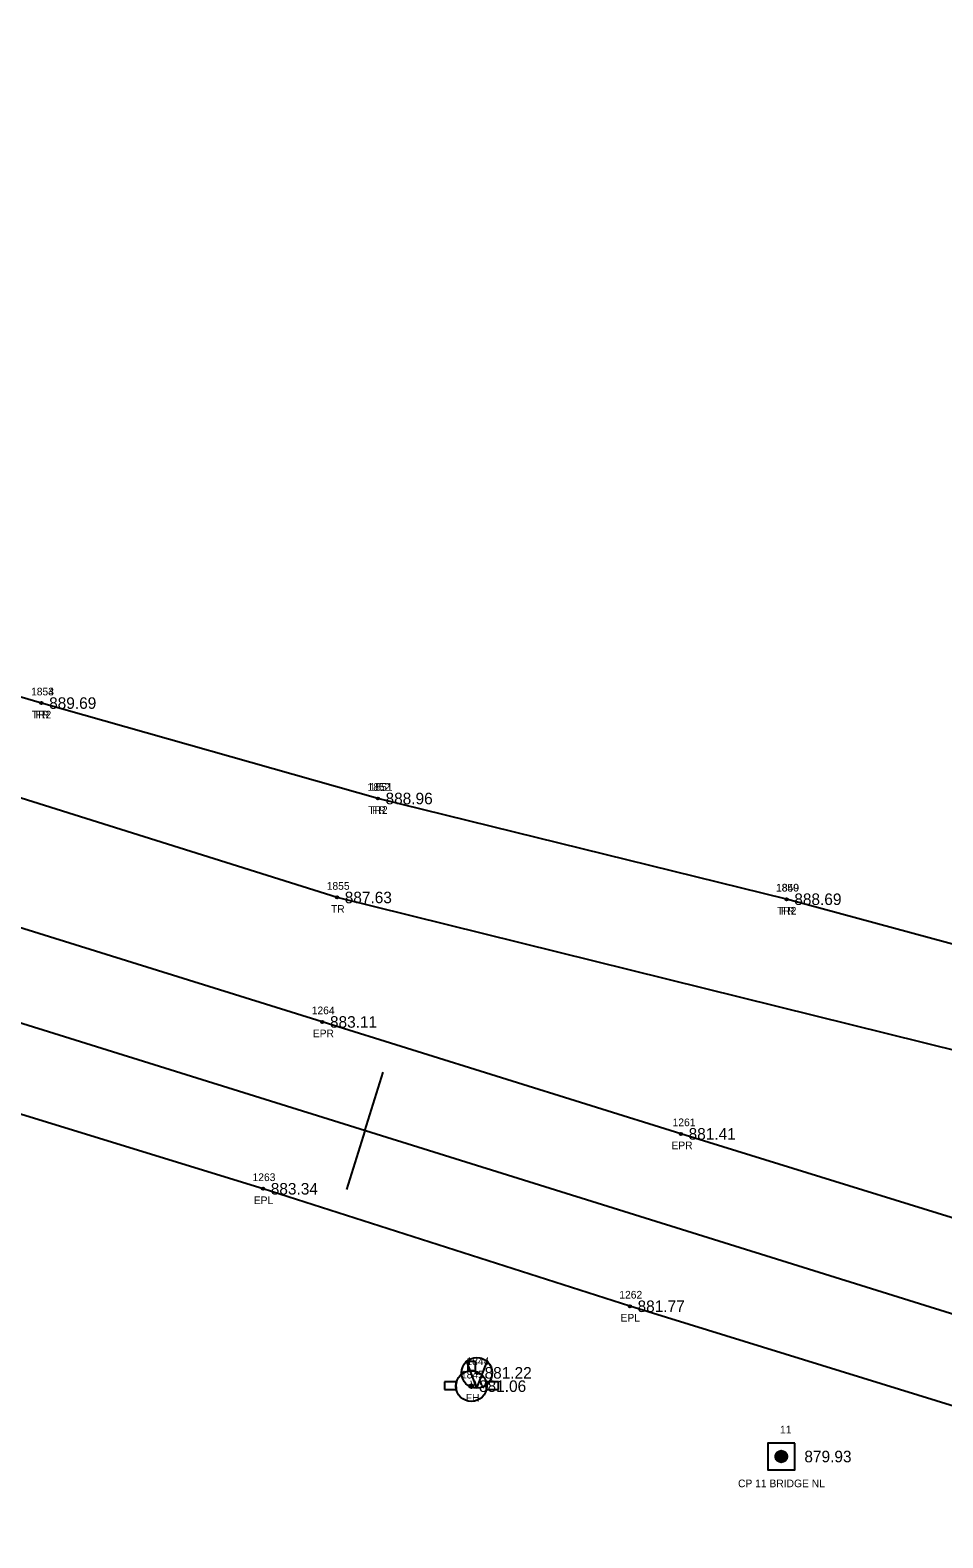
# Model space of a CAD drawing. Extents: x 1448136 to 1453623, y 1125056 to 1128842.
# Drawn here: x 1449871.2 to 1449990, y 1126660.1 to 1126856.2 of the extents above; entities that cross this region are included whole.
import ezdxf

# ---------------------------------------------------------------- set-up
doc = ezdxf.new("R2010")
doc.units = 0
for name, color, linetype in [('RD_EX_Fence_Other', 7, 'Continuous'), ('RD_EX_Fence_Other_txCode', 7, 'Continuous'), ('RD_EX_Road', 7, 'Continuous'), ('RD_EX_Road_txCode', 7, 'Continuous'), ('RD_EX_TX_Fence_Other_ELEV', 7, 'Continuous'), ('RD_EX_TX_Road_ELEV', 7, 'Continuous'), ('RD_EX_TX_UT_ELEV', 7, 'Continuous'), ('RD_EX_TX_VEG_ELEV', 7, 'Continuous'), ('RD_EX_UT', 7, 'Continuous'), ('RD_EX_UT_txCode', 7, 'Continuous'), ('RD_EX_VEG', 7, 'Continuous'), ('RD_EX_VEG_txCode', 7, 'Continuous'), ('RD_HC_Cl', 7, 'Continuous'), ('RD_HC_Data_Tic', 7, 'Continuous'), ('RD_HC_Survey', 7, 'Continuous'), ('RD_HC_Survey_ELEV', 7, 'Continuous'), ('RD_HC_Survey_txCode', 7, 'Continuous'), ('RD_SMD_Locator', 7, 'Continuous')]:
    doc.layers.add(name, color=color, linetype=linetype)

msp = doc.modelspace()

# ---------------------------------------------------------------- linework, layer by layer
at = {"layer": 'RD_EX_Fence_Other'}
msp.add_lwpolyline([(1450056.89, 1126784.04), (1450047.15, 1126748.04), (1450041.18, 1126724.82), (1450011.35, 1126731.86), (1449969.63, 1126743.17), (1449916.46, 1126756.27), (1449872.7, 1126768.68), (1449825.21, 1126782.55), (1449770.87, 1126786.35)], dxfattribs=at)
at = {"layer": 'RD_EX_Road'}
for points in [[(1450334.81, 1126677.22), (1450288.34, 1126667.77), (1450239.92, 1126662.52), (1450192.72, 1126661.45), (1450145.26, 1126665.09), (1450097.34, 1126672.81), (1450049.7, 1126684.25), (1450007.41, 1126696.7), (1449955.88, 1126712.65), (1449909.23, 1126727.21), (1449862.31, 1126741.85), (1449813.73, 1126756.84), (1449766.18, 1126771.72), (1449717.33, 1126787.19), (1449671.79, 1126801.4), (1449624.98, 1126815.8), (1449576.84, 1126830.74), (1449569.21, 1126834.03), (1449511.24, 1126851.67), (1449482.54, 1126860.68), (1449432.31, 1126877.02)], [(1450340.73, 1126655.01), (1450291.74, 1126645.33), (1450242.07, 1126639.91), (1450191.92, 1126637.95), (1450184.99, 1126636.16), (1450163.38, 1126634.92), (1450141.93, 1126638.08), (1450123.3, 1126641.98), (1450121.61, 1126644.88), (1450093.17, 1126650), (1450044.99, 1126661.93), (1449996.8, 1126675.54), (1449949.24, 1126690.23), (1449901.53, 1126705.51), (1449854.27, 1126720.01), (1449807.04, 1126735.02), (1449759.58, 1126749.86), (1449712.08, 1126764.7), (1449664.51, 1126779.32), (1449616.94, 1126794.11), (1449569.36, 1126808.87), (1449521.79, 1126823.57), (1449474.36, 1126838.35), (1449426.72, 1126853.6)]]:
    msp.add_lwpolyline(points, dxfattribs=at)
at = {"layer": 'RD_EX_UT'}
for p, q in [((1449929.34, 1126679.58), (1449928.04, 1126683.06)), ((1449928.16, 1126683.06), (1449928.16, 1126681.79)), ((1449929.16, 1126683.06), (1449928.16, 1126683.06)), ((1449929.16, 1126681.76), (1449929.16, 1126683.06)), ((1449929.34, 1126679.58), (1449930.66, 1126683.03)), ((1449926.7, 1126680.41), (1449925.14, 1126680.41)), ((1449925.14, 1126680.41), (1449925.14, 1126679.41)), ((1449925.14, 1126679.41), (1449926.66, 1126679.41)), ((1449932.14, 1126680.41), (1449930.53, 1126680.41)), ((1449930.57, 1126679.41), (1449932.14, 1126679.41)), ((1449932.14, 1126679.41), (1449932.14, 1126680.41))]:
    msp.add_line(p, q, dxfattribs=at)
for centre, radius in [((1449929.34, 1126681.57), 2), ((1449928.62, 1126679.84), 2), ((1449928.62, 1126679.84), 0.25)]:
    msp.add_circle(centre, radius, dxfattribs=at)
for start, end in [(74.2455, 103.2128), (163.3387, 192.315), (347.685, 16.6613)]:
    msp.add_arc((1449928.62, 1126679.84), 2, start, end, dxfattribs=at)
at = {"layer": 'RD_EX_VEG'}
for points in [[(1450497.14, 1126869.56), (1450516.22, 1126848.5), (1450549.56, 1126811.53), (1450532.56, 1126794.68), (1450460.23, 1126747.26), (1450374.14, 1126711.58), (1450359.93, 1126714.38), (1450327.4, 1126704.15), (1450192.75, 1126708.95), (1450138.86, 1126723.3), (1450098.59, 1126713.39), (1450034.93, 1126708.87), (1450011.45, 1126718.54), (1449911.15, 1126743.4), (1449863.97, 1126758.23), (1449819.7, 1126776.41), (1449751.34, 1126795.1)], [(1450056.89, 1126784.04), (1450047.15, 1126748.04), (1450041.18, 1126724.82), (1450011.35, 1126731.86), (1449969.63, 1126743.17), (1449916.46, 1126756.27), (1449872.7, 1126768.68), (1449825.21, 1126782.55), (1449751.34, 1126795.1)]]:
    msp.add_lwpolyline(points, dxfattribs=at)
at = {"layer": 'RD_HC_Cl'}
msp.add_line((1450033.34, 1126676.03), (1449295.29, 1126906.46), dxfattribs=at)
at = {"layer": 'RD_HC_Data_Tic'}
for q in [(1449917.15, 1126720.69), (1449912.38, 1126705.41)]:
    msp.add_line((1449914.76, 1126713.05), q, dxfattribs=at)
at = {"layer": 'RD_HC_Survey'}
for p, q in [((1449968.86, 1126669.92), (1449968.86, 1126671.45)), ((1449968.88, 1126669.92), (1449968.88, 1126671.45)), ((1449968.91, 1126669.92), (1449968.91, 1126671.46)), ((1449968.93, 1126669.92), (1449968.93, 1126671.46)), ((1449968.95, 1126669.92), (1449968.95, 1126671.46)), ((1449968.98, 1126669.92), (1449968.98, 1126671.45)), ((1449969, 1126669.92), (1449969, 1126671.45)), ((1449969.03, 1126669.92), (1449969.03, 1126671.45)), ((1449968.19, 1126670.51), (1449968.19, 1126670.87)), ((1449968.21, 1126670.42), (1449968.21, 1126670.95)), ((1449968.24, 1126670.36), (1449968.24, 1126671.01)), ((1449968.26, 1126670.32), (1449968.26, 1126671.06)), ((1449968.29, 1126670.27), (1449968.29, 1126671.1)), ((1449968.31, 1126670.24), (1449968.31, 1126671.14)), ((1449968.34, 1126670.2), (1449968.34, 1126671.17)), ((1449968.36, 1126670.18), (1449968.36, 1126671.2)), ((1449968.39, 1126670.15), (1449968.39, 1126671.22)), ((1449968.41, 1126670.12), (1449968.41, 1126671.25)), ((1449968.44, 1126670.1), (1449968.44, 1126671.27)), ((1449968.46, 1126670.08), (1449968.46, 1126671.29)), ((1449968.48, 1126670.06), (1449968.48, 1126671.31)), ((1449968.51, 1126670.05), (1449968.51, 1126671.33)), ((1449968.53, 1126670.03), (1449968.53, 1126671.34)), ((1449968.56, 1126670.02), (1449968.56, 1126671.36)), ((1449968.58, 1126670), (1449968.58, 1126671.37)), ((1449968.61, 1126669.99), (1449968.61, 1126671.38)), ((1449968.63, 1126669.98), (1449968.63, 1126671.39)), ((1449968.66, 1126669.97), (1449968.66, 1126671.4)), ((1449968.68, 1126669.96), (1449968.68, 1126671.41)), ((1449968.71, 1126669.95), (1449968.71, 1126671.42)), ((1449968.73, 1126669.94), (1449968.73, 1126671.43)), ((1449968.76, 1126669.94), (1449968.76, 1126671.43)), ((1449968.78, 1126669.93), (1449968.78, 1126671.44)), ((1449968.81, 1126669.93), (1449968.81, 1126671.44)), ((1449968.83, 1126669.92), (1449968.83, 1126671.45)), ((1449969.05, 1126669.93), (1449969.05, 1126671.45)), ((1449969.08, 1126669.93), (1449969.08, 1126671.44)), ((1449969.1, 1126669.94), (1449969.1, 1126671.44)), ((1449969.13, 1126669.94), (1449969.13, 1126671.43)), ((1449969.15, 1126669.95), (1449969.15, 1126671.42)), ((1449969.18, 1126669.96), (1449969.18, 1126671.42)), ((1449969.2, 1126669.96), (1449969.2, 1126671.41)), ((1449969.23, 1126669.97), (1449969.23, 1126671.4)), ((1449969.25, 1126669.98), (1449969.25, 1126671.39)), ((1449969.28, 1126670), (1449969.28, 1126671.38)), ((1449969.3, 1126670.01), (1449969.3, 1126671.36)), ((1449969.33, 1126670.02), (1449969.33, 1126671.35)), ((1449969.35, 1126670.04), (1449969.35, 1126671.33)), ((1449969.38, 1126670.05), (1449969.38, 1126671.32)), ((1449969.4, 1126670.07), (1449969.4, 1126671.3)), ((1449969.42, 1126670.09), (1449969.42, 1126671.28)), ((1449969.45, 1126670.11), (1449969.45, 1126671.26)), ((1449969.47, 1126670.14), (1449969.47, 1126671.24)), ((1449969.5, 1126670.16), (1449969.5, 1126671.21)), ((1449969.52, 1126670.19), (1449969.52, 1126671.18)), ((1449969.55, 1126670.22), (1449969.55, 1126671.15)), ((1449969.57, 1126670.26), (1449969.57, 1126671.12)), ((1449969.6, 1126670.29), (1449969.6, 1126671.08)), ((1449969.62, 1126670.34), (1449969.62, 1126671.03)), ((1449969.65, 1126670.39), (1449969.65, 1126670.98)), ((1449969.67, 1126670.46), (1449969.67, 1126670.91)), ((1449969.7, 1126670.57), (1449969.7, 1126670.8))]:
    msp.add_line(p, q, dxfattribs=at)
msp.add_lwpolyline([(1449970.69, 1126672.44), (1449967.19, 1126672.44), (1449967.19, 1126668.94), (1449970.69, 1126668.94)], close=True, dxfattribs=at)
msp.add_circle((1449968.94, 1126670.69), 0.769, dxfattribs=at)
at = {"layer": 'RD_SMD_Locator'}
for centre in [(1449872.7, 1126768.68), (1449872.7, 1126768.68), (1449916.46, 1126756.27), (1449916.46, 1126756.27), (1449911.15, 1126743.4), (1449969.63, 1126743.17), (1449969.63, 1126743.17), (1449909.23, 1126727.21), (1449955.88, 1126712.65), (1449901.53, 1126705.51), (1449949.24, 1126690.23), (1449929.34, 1126681.57), (1449928.62, 1126679.84), (1449968.94, 1126670.69)]:
    msp.add_circle(centre, 0.15, dxfattribs=at)

# ---------------------------------------------------------------- texts
at = {"layer": 'RD_EX_Fence_Other_txCode'}
for s, p in [('1853', (1449871.35, 1126769.68)), ('FR', (1449871.94, 1126766.68)), ('1851', (1449915.39, 1126757.27)), ('FR', (1449915.7, 1126754.27)), ('1850', (1449968.24, 1126744.17)), ('FR', (1449968.87, 1126741.17))]:
    msp.add_text(s, height=1, dxfattribs=at).set_placement(p)
at = {"layer": 'RD_EX_Road_txCode'}
for s, p in [('1264', (1449907.86, 1126728.21)), ('EPR', (1449908, 1126725.21)), ('1261', (1449954.8, 1126713.65)), ('EPR', (1449954.65, 1126710.65)), ('1263', (1449900.16, 1126706.51)), ('EPL', (1449900.32, 1126703.51)), ('1262', (1449947.87, 1126691.23)), ('EPL', (1449948.03, 1126688.23))]:
    msp.add_text(s, height=1, dxfattribs=at).set_placement(p)
at = {"layer": 'RD_EX_TX_Fence_Other_ELEV'}
for s, p in [('889.69', (1449873.7, 1126767.93)), ('888.96', (1449917.46, 1126755.52)), ('888.69', (1449970.63, 1126742.42))]:
    msp.add_text(s, height=1.5, dxfattribs=at).set_placement(p)
at = {"layer": 'RD_EX_TX_Road_ELEV'}
for s, p in [('883.11', (1449910.23, 1126726.46)), ('881.41', (1449956.88, 1126711.9)), ('883.34', (1449902.53, 1126704.76)), ('881.77', (1449950.24, 1126689.48))]:
    msp.add_text(s, height=1.5, dxfattribs=at).set_placement(p)
at = {"layer": 'RD_EX_TX_UT_ELEV'}
for s, p in [('881.22', (1449930.34, 1126680.82)), ('881.06', (1449929.62, 1126679.09))]:
    msp.add_text(s, height=1.5, dxfattribs=at).set_placement(p)
at = {"layer": 'RD_EX_TX_VEG_ELEV'}
for s, p in [('889.69', (1449873.7, 1126767.93)), ('888.96', (1449917.46, 1126755.52)), ('887.63', (1449912.15, 1126742.65)), ('888.69', (1449970.63, 1126742.42))]:
    msp.add_text(s, height=1.5, dxfattribs=at).set_placement(p)
at = {"layer": 'RD_EX_UT_txCode'}
for s, p in [('1844', (1449927.99, 1126682.57)), ('1845', (1449927.27, 1126680.84)), ('WV', (1449928.48, 1126679.57)), ('FH', (1449927.89, 1126677.84))]:
    msp.add_text(s, height=1, dxfattribs=at).set_placement(p)
at = {"layer": 'RD_EX_VEG_txCode'}
for s, p in [('1854', (1449871.35, 1126769.68)), ('TR2', (1449871.45, 1126766.68)), ('1852', (1449915.11, 1126757.27)), ('TR2', (1449915.21, 1126754.27)), ('1855', (1449909.81, 1126744.4)), ('1849', (1449968.28, 1126744.17)), ('TR', (1449910.36, 1126741.4)), ('TR2', (1449968.38, 1126741.17))]:
    msp.add_text(s, height=1, dxfattribs=at).set_placement(p)
at = {"layer": 'RD_HC_Survey_ELEV'}
msp.add_text('879.93', height=1.5, dxfattribs=at).set_placement((1449971.94, 1126669.94))
at = {"layer": 'RD_HC_Survey_txCode'}
for s, p in [('11', (1449968.77, 1126673.69)), ('CP 11 BRIDGE NL', (1449963.31, 1126666.69))]:
    msp.add_text(s, height=1, dxfattribs=at).set_placement(p)

doc.saveas('drawing.dxf')
